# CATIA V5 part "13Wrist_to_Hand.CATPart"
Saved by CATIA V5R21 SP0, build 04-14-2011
Part number: Wrist_to_Hand
Bounding box of the stored display mesh (mm): x -25 to 5, y -16.902 to 24.098, z -24.703 to 25.297
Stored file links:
  C:\Users\水心\Desktop\Arm_Detailed_Design_Assembly_Manu\13Wrist_to_Hand.CATPart
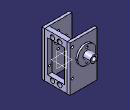
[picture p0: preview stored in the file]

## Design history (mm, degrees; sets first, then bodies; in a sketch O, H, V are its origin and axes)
Body1 "Plate1" (main body)
  Sketch1 on yz-plane, origin (0, 0, 0), H (0, 1, 0), V (0, 0, 1)
    line L1 (-13.9025, 25.2974) -> (11.0975, 25.2974)
    line L2 (11.0975, 25.2974) -> (11.0975, -24.7026)
    line L3 (11.0975, -24.7026) -> (-13.9025, -24.7026)
    line L4 (-13.9025, -24.7026) -> (-13.9025, 25.2974)
    point P5 (-5.4025, -20.2026)
    point P6 (2.5975, -20.2026)
    axis line L5 (-30.6382, 0.2974) -> (38.767, 0.2974)
    line L6 (8.0975, 18.0474) -> (8.0975, -17.4526)
    line L7 (-10.9025, -17.4526) -> (-10.9025, 18.0474)
    point P11 (8.0975, -17.4526)
    point P12 (-10.9025, -17.4526)
    circle A1 centre (-5.4025, -20.2026) radius 2.5
    circle A2 centre (2.5975, -20.2026) radius 2.5
    line L8 (-10.9025, -17.4526) -> (8.0975, -17.4526)
    circle A3 centre (-5.4025, 20.7974) radius 2.5
    point P14 (8.0975, 18.0474)
    point P15 (-10.9025, 18.0474)
    line L9 (-10.9025, 18.0474) -> (8.0975, 18.0474)
    circle A4 centre (2.5975, 20.7974) radius 2.5
    length L1 = 25
    length L2 = 50
    distance P5 L3 = 4.5
    distance P6 L3 = 4.5
    distance P5 P6 = 8
    distance P5 L4 = 8.5
    distance L5 L3 = 25
    distance L6 L2 = 3
    distance L7 L4 = 3
    radius A2 = 2.5
    radius A1 = 2.5
    horizontal: L1 H, L3 H, L5 H, L8 H
    vertical: L2 V, L4 V, L6 V, L7 V
    symmetry: A1 A3 L5, P11 P14 L5, P12 P15 L5, L8 L9 L5, A2 A4 L5
  Pad1: profile Sketch1, direction (1, 0, 0), length 5
  Sketch2 on face of Pad1 from Sketch1.L4, origin (0, -13.9025, 0), H (1, 0, 0), V (0, 0, 1)
    circle A1 centre (2.5, 20.2974) radius 1.25
    point P1 (2.5, 20.2974)
    circle A2 centre (2.5, -9.7026) radius 1.25
    point P2 (2.5, -9.7026)
    reference projected line E1 (0, -24.7026) -> (5, -24.7026) from edge [face of Pad1 from Sketch1.L3 | face of Pad1 from Sketch1.L4]
    reference projected line E2 (0, 25.2974) -> (0, -24.7026) from edge [start face of Pad1 | face of Pad1 from Sketch1.L4]
    reference projected line E3 (0, 25.2974) -> (5, 25.2974) from edge [face of Pad1 from Sketch1.L4 | face of Pad1 from Sketch1.L1]
    reference projected line E4 (0, 25.2974) -> (0, -24.7026) from edge [start face of Pad1 | face of Pad1 from Sketch1.L4]
    radius A2 = 1.25
    distance P2 E1 = 15
    distance P2 E2 = 2.5
    distance P1 E3 = 5
    radius A1 = 1.25
    distance P1 E4 = 2.5
  Pocket1: profile Sketch2, direction (0, 1, 0), length 4
  Sketch3 on face of Pad1 from Sketch1.L2, origin (0, 11.0975, 0), H (-1, 0, 0), V (0, 0, 1)
    circle A1 centre (-2.5, 20.2974) radius 1.25
    point P1 (-2.5, 20.2974)
    circle A2 centre (-2.5, -9.7026) radius 1.25
    point P2 (-2.5, -9.7026)
    reference projected line E1 (0, -24.7026) -> (-5, -24.7026) from edge [face of Pad1 from Sketch1.L2 | face of Pad1 from Sketch1.L3]
    reference projected line E2 (-5, -24.7026) -> (-5, 25.2974) from edge [face of Pad1 from Sketch1.L2 | end face of Pad1]
    reference projected line E3 (-5, -24.7026) -> (-5, 25.2974) from edge [face of Pad1 from Sketch1.L2 | end face of Pad1]
    reference projected line E4 (0, 25.2974) -> (-5, 25.2974) from edge [face of Pad1 from Sketch1.L1 | face of Pad1 from Sketch1.L2]
    radius A2 = 1.25
    distance P2 E1 = 15
    distance P2 E2 = 2.5
    distance P1 E3 = 2.5
    radius A1 = 1.25
    distance P1 E4 = 5
  Pocket2: profile Sketch3, direction (0, -1, 0), length 4
Body2 "Plate2"
  Sketch4 on face of Pad1 from Sketch1.L4, origin (0, -13.9025, 0), H (1, 0, 0), V (0, 0, 1)
    line L1 (-25, 25.2974) -> (5, 25.2974)
    line L2 (5, 25.2974) -> (5, -24.7026)
    line L3 (5, -24.7026) -> (-25, -24.7026)
    line L4 (-25, -24.7026) -> (-25, 25.2974)
    reference projected line E1 (0, 25.2974) -> (5, 25.2974) from edge [face of Pad1 from Sketch1.L4 | face of Pad1 from Sketch1.L1]
    reference projected line E2 (0, -24.7026) -> (5, -24.7026) from edge [face of Pad1 from Sketch1.L3 | face of Pad1 from Sketch1.L4]
    reference projected line E3 (5, 25.2974) -> (5, -24.7026) from edge [face of Pad1 from Sketch1.L4 | end face of Pad1]
    circle A1 centre (-10, 7.0474) radius 4
    point P5 (-10, 7.0474)
    circle A2 centre (-10, 15.5474) radius 1.25
    point P6 (-10, 15.5474)
    circle A3 centre (2.5, 20.2974) radius 1.25
    point P7 (2.5, 20.2974)
    circle A4 centre (2.5, -9.7026) radius 1.25
    point P8 (2.5, -9.7026)
    circle A5 centre (-18.5, 7.0474) radius 1.25
    circle A6 centre (-10, -1.4526) radius 1.25
    circle A7 centre (-1.5, 7.0474) radius 1.25
    distance L2 L4 = 30
    distance P5 L2 = 15
    distance P5 L1 = 18.25
    radius A1 = 4
    radius A2 = 1.25
    distance P6 P5 = 8.5
    distance P6 L2 = 15
    radius A4 = 1.25
    distance P8 L2 = 2.5
    distance P8 L3 = 15
    radius A3 = 1.25
    distance P7 L1 = 5
    distance P7 L2 = 2.5
    horizontal: L1 H, L3 H
    vertical: L2 V, L4 V
    coincidence: L1 E1, L3 E2, L2 E3
  Pad2: profile Sketch4, direction (0, -1, 0), length 3
Body3 "Plate3"
  Sketch5 on face of Pad1 from Sketch1.L2, origin (0, 11.0975, 0), H (-1, 0, 0), V (0, 0, 1)
    line L1 (-5, 25.2974) -> (25, 25.2974)
    line L2 (25, 25.2974) -> (25, -24.7026)
    line L3 (25, -24.7026) -> (-5, -24.7026)
    line L4 (-5, -24.7026) -> (-5, 25.2974)
    construction circle A1 centre (11.5, 7.0474) radius 10
    point P5 (11.5, 7.0474)
    reference projected line E1 (-5, 25.2974) -> (25, 25.2974) from edge [start face of Pad2 | face of Pad2 from Sketch4.L1]
    reference projected line E2 (25, -24.7026) -> (-5, -24.7026) from edge [start face of Pad2 | face of Pad2 from Sketch4.L3]
    reference projected line E3 (-5, -24.7026) -> (-5, 25.2974) from edge [face of Pad1 from Sketch1.L2 | end face of Pad1]
    circle A2 centre (-2.5, 20.2974) radius 1.25
    point P6 (-2.5, 20.2974)
    circle A3 centre (-2.5, -9.7026) radius 1.25
    point P7 (-2.5, -9.7026)
    circle A4 centre (11.5, 14.0474) radius 1.25
    point P8 (11.5, 14.0474)
    circle A5 centre (11.5, 0.0474) radius 1.25
    point P9 (11.5, 0.0474)
    distance P5 L1 = 18.25
    distance P5 L4 = 16.5
    length L3 = 30
    radius A3 = 1.25
    distance P7 L3 = 15
    distance P7 L4 = 2.5
    distance P6 L4 = 2.5
    radius A2 = 1.25
    distance P6 L1 = 5
    radius A1 = 10
    distance P9 L4 = 16.5
    distance L4 P8 = 16.5
    distance P5 P8 = 7
    distance P9 P5 = 7
    radius A5 = 1.25
    radius A4 = 1.25
    horizontal: L1 H, L3 H
    vertical: L2 V, L4 V
    coincidence: L1 E1, L3 E2, L4 E3
  Pad3: profile Sketch5, direction (0, 1, 0), length 3
Body4 "Connect"
  Sketch6 on end face of Pad3, origin (0, 14.0975, 0), H (-1, 0, 0), V (0, 0, 1)
    circle A1 centre (11.5, 7.0474) radius 10
    point P1 (11.5, 7.0474)
    reference projected line E1 (25, 25.2974) -> (-5, 25.2974) from edge [face of Pad3 from Sketch5.L1 | end face of Pad3]
    reference projected line E2 (-5, 25.2974) -> (-5, -24.7026) from edge [face of Pad3 from Sketch5.L4 | end face of Pad3]
    circle A2 centre (11.5, 14.0474) radius 1.25
    point P2 (11.5, 14.0474)
    circle A3 centre (11.5, 0.0474) radius 1.25
    point P3 (11.5, 0.0474)
    reference projected line E3 (-5, 25.2974) -> (-5, -24.7026) from edge [face of Pad3 from Sketch5.L4 | end face of Pad3]
    reference projected line E4 (-5, 25.2974) -> (-5, -24.7026) from edge [face of Pad3 from Sketch5.L4 | end face of Pad3]
    radius A1 = 10
    distance P1 E1 = 18.25
    distance P1 E2 = 16.5
    radius A2 = 1.25
    radius A3 = 1.25
    distance P3 P1 = 7
    distance P2 P1 = 7
    distance P3 E3 = 16.5
    distance P2 E4 = 16.5
  Pad4: profile Sketch6, direction (0, 1, 0), length 2
  Sketch7 on end face of Pad4, origin (0, 16.0975, 0), H (-1, 0, 0), V (0, 0, 1)
    circle A1 centre (11.5, 7.0474) radius 4.1
    reference projected circle E1 centre (11.5, 7.0474) radius 10 from edge [face of Pad4 from Sketch6.A1 | end face of Pad4]
    circle A2 centre (11.5, 7.0474) radius 2.5
    radius A1 = 4.1
    radius A2 = 2.5
    concentricity: A1 E1
  Pad5: profile Sketch7, direction (0, 1, 0), length 8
